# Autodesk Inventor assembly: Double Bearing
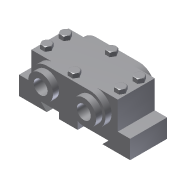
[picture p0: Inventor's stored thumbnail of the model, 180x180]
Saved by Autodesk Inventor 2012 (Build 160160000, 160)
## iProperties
Shininess: 64.0
Length Units: 11269
Angle Units: 11279
Time Units: 11290
Mass Units: 11283
Length Display Precision: 3
Angle Display Precision: 2
Created: 2002-02
Part Number: Double Bearing
Document SubType Name: Assembly
Designer: ***
Density: 0.0
Volumn: 0.0
Area: 0.0
PropertySet Name: Model Information
Control State: 0
Master: False
Checked Out: False
Author: ***
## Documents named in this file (5)
- C:\Users\CadCim\Documents\SAILESH\inventor-2011-fact-prt\c1211inv_2012-prt\c12_inv_2012_prt\fig-12-10 and 12-18\Double Bearing.iam
- C:\Users\CadCim\Documents\SAILESH\inventor-2011-fact-prt\c1211inv_2012-prt\fig-12-10 and 12-18\Base.ipt
- C:\Users\CadCim\Documents\SAILESH\inventor-2011-fact-prt\c1211inv_2012-prt\fig-12-10 and 12-18\Cap.ipt
- C:\Users\CadCim\Documents\SAILESH\inventor-2011-fact-prt\c1211inv_2012-prt\fig-12-10 and 12-18\Bushing.ipt
- C:\Users\CadCim\Documents\SAILESH\inventor-2011-fact-prt\c1211inv_2012-prt\fig-12-10 and 12-18\Bolt.ipt
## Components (10 placed, 4 different names)
1. Base:1 — Insert:1, Insert:2
2. Cap:1 — Insert:1, Insert:2, Insert:3, Insert:4, Insert:5, Insert:6
3. Bushing:1 — Insert:3
4. Bushing:2 — Insert:4
5. Bolt:1 — Insert:5
6. Bolt:6
7. Bolt:7
8. Bolt:8
9. Bolt:5 — Insert:6
10. Bolt:9
## Component patterns: Component Pattern 1 (4 elements), Component Pattern 2 (2 elements)
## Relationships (6: Insert 6)
- Insert:1: Base:1 ↔ Cap:1
- Insert:2: Base:1 ↔ Cap:1
- Insert:3: Cap:1 ↔ Bushing:1
- Insert:4: Cap:1 ↔ Bushing:2
- Insert:5: Cap:1 ↔ Bolt:1
- Insert:6: Cap:1 ↔ Bolt:5
